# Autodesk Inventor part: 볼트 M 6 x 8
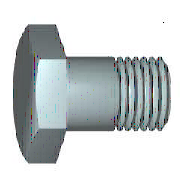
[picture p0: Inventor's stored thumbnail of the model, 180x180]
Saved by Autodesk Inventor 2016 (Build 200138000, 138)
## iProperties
Created: 2012-02
Part Number: 볼트 M 6 x 8
Material: 강철, 연강
Description: 6각 머리 볼트 및 6각 머리 나사
Document SubType Name: Modeling
Standard: KS B 1002
Designer: mduedu
Standards Organization: KS
Language: ko-KR
Size Designation: C  M 6 x 12
Categories: <MemberInstance><Categories><Category DisplayName="조임쇠" InternalName="e4da775c-781d-43d5-af7c-5136215cf5a6" Mnemonic="FSTN"><Category DisplayName="볼트" InternalN
Density: 1 g/cm^3
Appearance: 강철
IsCustomPart: 1
Author: mduedu
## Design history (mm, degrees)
sketch "스케치1"
  geometry: L1 (0, 3)-(8, 3); L2 (8, 3)-(8, 0); L3 (8, 0)-(0, 0); L4 (-2.4, 0)-(14.4, 0) reference; L5 (0, -0.6)-(0, 3.6) reference; L6 (0, 3)-(0, 0)
  constraints: 8 end point, 3 point on line, 1 collinear
  dimensions: "d2" = 6 diameter of L1 L3 (= GD); "d59" = 8 distance between parallel lines of L2 L5 (= NLG)
revolve "본체" sketch "스케치1" stored, may be unused: angle "d12" = 90 deg
sketch "스케치2"
  geometry: L1 (0, 5.774)-(5, 2.887); L2 (5, 2.887)-(5, -2.887); L3 (5, -2.887)-(0, -5.774); L4 (0, -5.774)-(-5, -2.887); L5 (-5, -2.887)-(-5, 2.887); L6 (-5, 2.887)-(0, 5.774); L7 (-7, 0)-(7, 0) reference; L8 (0, 8.083)-(0, -8.083) reference; 2 further points
  constraints: 12 end point, 2 midpoint, 1 coincident, 1 vertical, 11 other
  dimensions: "d11" = 10 distance between parallel lines of L5 L2 (= SW)
extrude "머리" join sketch "스케치2" distance "d3" = 4 (= KOH); taper "d4" = 0 deg
revolve "모따기1" stored, may be unused: angle "d21" = 90 deg
workplane "Work Plane1"
body "Solid1"
feature "스레드" dims "d15" = 9 (= GEL), "d16" = 0
chamfer "모따기2" distance "d6" = 0.61345 (= -0.5 x SPD + 0.5 x GD); stored, may be unused: second distance "d7" = 0.61355 (computed from GUL), angle "d55" = 45 deg
sketch "스케치4"
  geometry: L1 (-3.423, 6)-(-4, 5); L2 (-1.1, 0)-(-0.234, 0); L3 (-4.753, 0)-(0.519, 0) reference; L4 (-4, 6)-(-3.423, 6); L5 (-4, 5)-(-4, 6); L6 (0, 7.2)-(0, -1.2) reference
  constraints: 8 end point, 1 parallel, 1 perpendicular, 1 point on line
  dimensions: "d65" = 10 diameter of L1.end L2 (= SW); "d67" = 30 deg angle of L1 L5 (= ANG1); "d68" = 12 diameter of L4 L2 (= 1.2 x SW); "d69" = 4 distance between parallel lines of L5 L6 (= KOH)
other parameters: "NLG" = 8 [user parameter; used in 1 equation term], "GD" = 6 (= NND) [user parameter; used in 2 equation terms], "BDM" = 6 (= NND) [user parameter], "KOH" = 4 [user parameter; used in 2 equation terms], "GEL" = 9 [user parameter; used in 1 equation term], "SW" = 10 [user parameter; used in 5 equation terms], "SPD" = 4.7731 (= NND - 1.2269 x PTC) [user parameter; used in 1 equation term], "SD2" = 6 (= NND) [user parameter], "SD" = 0 [user parameter], "ANG1" = 30 deg [user parameter; used in 1 equation term], "GAL" = 0.61345 (= 0.61345 x PTC) [user parameter], "GUL" = 0.61345 (= 0.61345 x PTC) [user parameter; used in 1 equation term], "d8" = 0, "RR" = 0.25 [user parameter], "d58" = 0, "RR1" = 0.1 [user parameter], "GD1" = 4.7731 (= THREADDIA - 1.2269 x PTC) [user parameter], "THREADDIA" = 6 [user parameter; used in 1 equation term], "TOA" = 30 deg [user parameter], "PTC" = 1 [user parameter; used in 5 equation terms], "NND" = 6 [user parameter; used in 4 equation terms], "E0" = 11.55 (= 1.155 x SW) [user parameter]
